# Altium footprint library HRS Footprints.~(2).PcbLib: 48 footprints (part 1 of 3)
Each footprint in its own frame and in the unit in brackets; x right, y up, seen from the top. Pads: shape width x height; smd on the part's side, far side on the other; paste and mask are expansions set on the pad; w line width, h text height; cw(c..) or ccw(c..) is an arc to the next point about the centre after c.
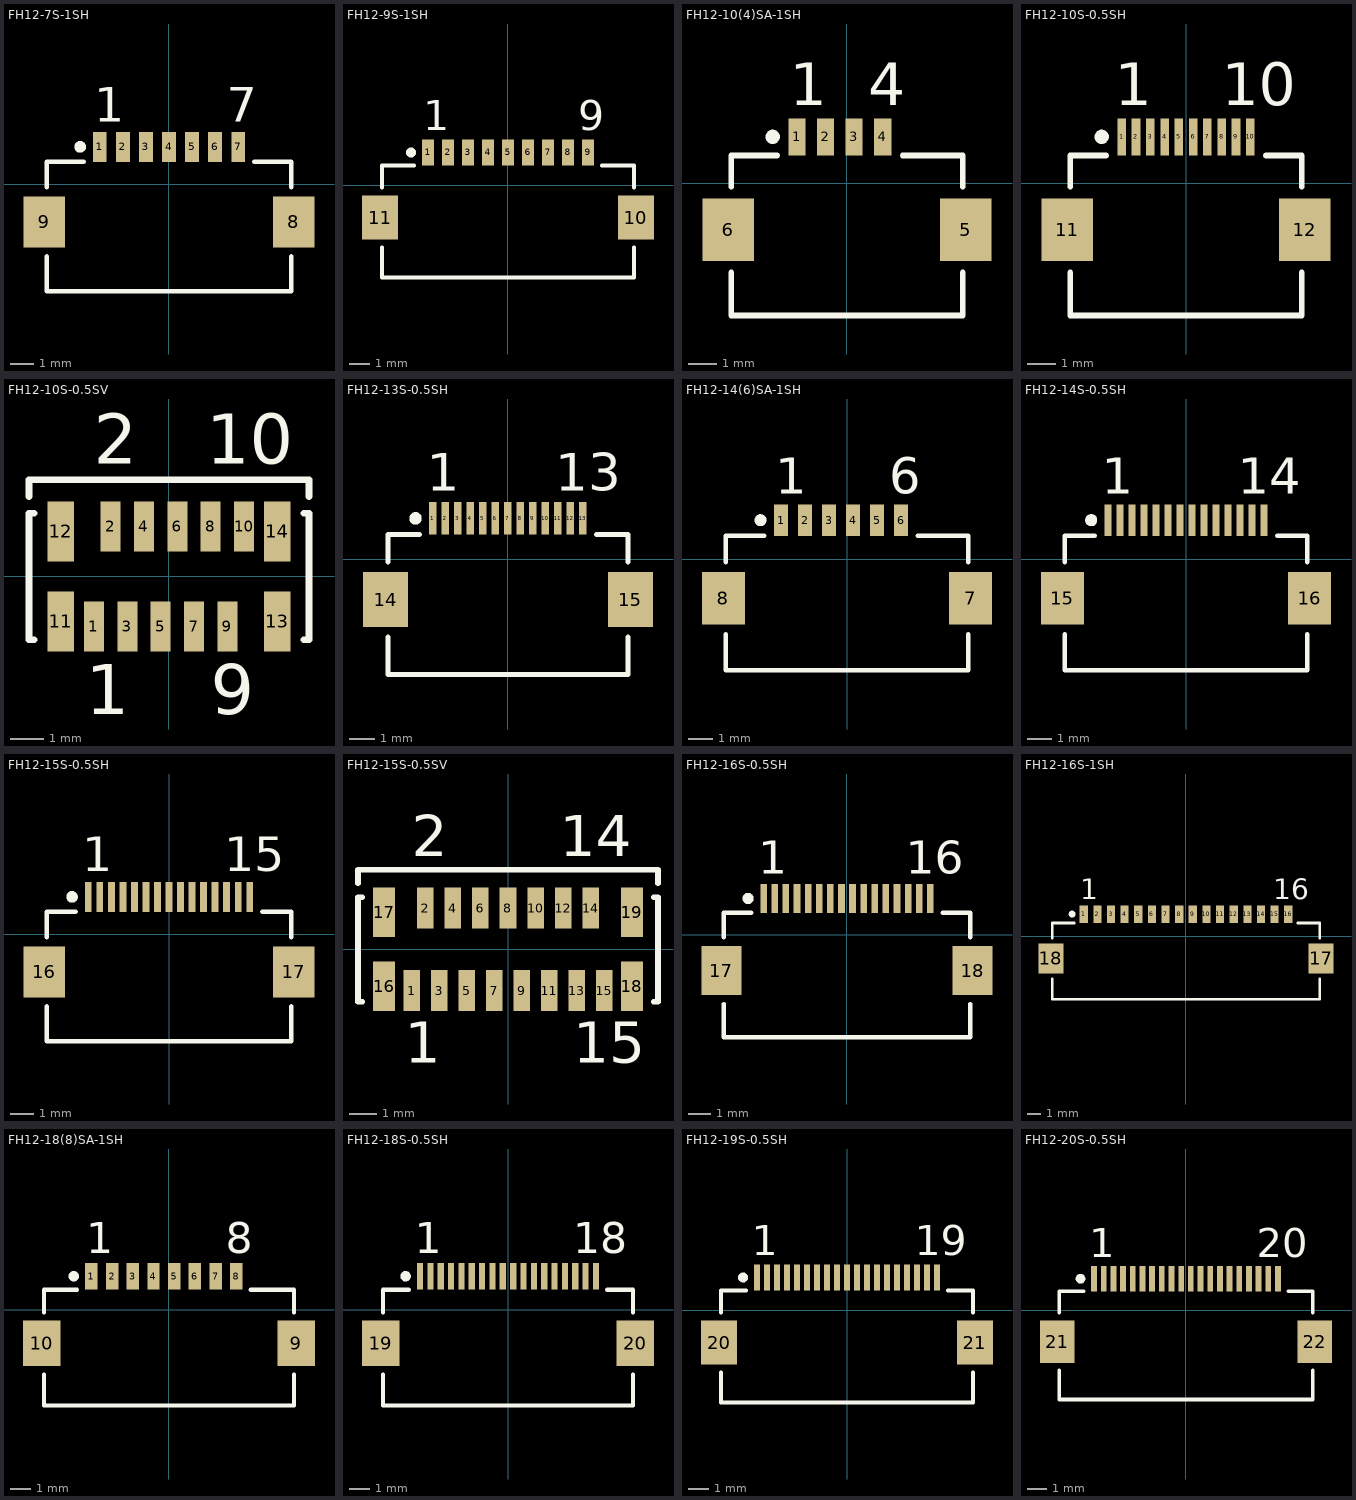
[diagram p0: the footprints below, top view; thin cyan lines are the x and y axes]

## FH12-7S-1SH [mm] "Connector; FH12 Series; 7 Position; 1.0mm Spaced Bottom Standard Contact"
height 2
pads (9):
  rect 0.6x1.3 smd: 1(-3,1.625) 2(-2,1.625) 3(-1,1.625) 4(0,1.625) 5(1,1.625) 6(2,1.625) 7(3,1.625)
  rect 1.8x2.2 smd: 8(5.4,-1.625) 9(-5.4,-1.625)
Top Overlay:
  circle w0.25: c-3.85,1.625 r0.125
  lines w0.2: -5.3,-3.125 -5.3,-4.625 5.3,-4.625 5.3,-3.125 ; -5.3,-0.125 -5.3,0.975 -3.7,0.975 ; 3.7,0.975 5.3,0.975 5.3,-0.125
  text "1" at -3.25,2.725 h1.5
  text "7" at 2.5,2.725 h1.5

## FH12-9S-1SH [mm] "Connector; FH12 Series; 9 Position; 1.0mm Spaced Bottom Standard Contact"
height 2
pads (11):
  rect 0.6x1.3 smd: 1(-4,1.625) 2(-3,1.625) 3(-2,1.625) 4(-1,1.625) 5(0,1.625) 6(1,1.625) 7(2,1.625) 8(3,1.625) 9(4,1.625)
  rect 1.8x2.2 smd: 10(6.4,-1.625) 11(-6.4,-1.625)
Top Overlay:
  circle w0.25: c-4.85,1.625 r0.125
  lines w0.2: -6.3,-3.125 -6.3,-4.625 6.3,-4.625 6.3,-3.125 ; -6.3,-0.125 -6.3,0.975 -4.7,0.975 ; 4.7,0.975 6.3,0.975 6.3,-0.125
  text "1" at -4.25,2.725 h1.5
  text "9" at 3.5,2.725 h1.5

## FH12-10(4)SA-1SH [mm] "Connector; FH12 Series; 4 Position; 1.0mm Spaced Bottom Eccentric Contact"
height 2
pads (6):
  rect 0.6x1.3 smd: 1(-1.75,1.625) 2(-0.75,1.625) 3(0.25,1.625) 4(1.25,1.625)
  rect 1.8x2.2 smd: 5(4.15,-1.625) 6(-4.15,-1.625)
Top Overlay:
  circle w0.25: c-2.6,1.625 r0.125
  lines w0.2: -4.05,-3.125 -4.05,-4.625 4.05,-4.625 4.05,-3.125 ; -4.05,-0.125 -4.05,0.975 -2.45,0.975 ; 1.95,0.975 4.05,0.975 4.05,-0.125
  text "4" at 0.75,2.725 h1.5
  text "1" at -2,2.725 h1.5

## FH12-10S-0.5SH [mm] "Connector; FH12 Series; 10 Position; 0.5mm Spaced Bottom Contact"
height 2
pads (12):
  rect 0.3x1.3 smd: 1(-2.25,1.625) 2(-1.75,1.625) 3(-1.25,1.625) 4(-0.75,1.625) 5(-0.25,1.625) 6(0.25,1.625) 7(0.75,1.625) 8(1.25,1.625) 9(1.75,1.625) 10(2.25,1.625)
  rect 1.8x2.2 smd: 11(-4.15,-1.625) 12(4.15,-1.625)
Top Overlay:
  circle w0.25: c-2.95,1.625 r0.125
  lines w0.2: -4.05,-3.125 -4.05,-4.625 4.05,-4.625 4.05,-3.125 ; -4.05,-0.125 -4.05,0.975 -2.8,0.975 ; 2.8,0.975 4.05,0.975 4.05,-0.125
  text "10" at 1.25,2.725 h1.5
  text "1" at -2.5,2.725 h1.5

## FH12-10S-0.5SV [mm] "Connector; FH12 Series; 10 Position; 0.5mm Spaced Vertical Mounting"
height 4.85
pads (14):
  rect 0.6x1.5 smd: 1(-2.25,-1.5) 2(-1.75,1.5) 3(-1.25,-1.5) 4(-0.75,1.5) 5(-0.25,-1.5) 6(0.25,1.5) 7(0.75,-1.5) 8(1.25,1.5) 9(1.75,-1.5) 10(2.25,1.5)
  rect 0.8x1.8 smd: 11(-3.25,-1.35) 12(-3.25,1.35) 13(3.25,-1.35) 14(3.25,1.35)
Top Overlay:
  lines w0.2: -4.2,2.4 -4.2,2.9 4.2,2.9 4.2,2.4 ; -4.05,-1.9 -4.2,-1.9 -4.2,1.9 -4.05,1.9 ; 4.05,-1.9 4.2,-1.9 4.2,1.9 4.05,1.9
  text "2" at -2.25,3.375 h1.5
  text "1" at -2.5,-4.125 h1.5
  text "10" at 1.125,3.375 h1.5
  text "9" at 1.25,-4.125 h1.5

## FH12-13S-0.5SH [mm] "Connector; FH12 Series; 13 Position; 0.5mm Spaced Bottom Contact"
height 2
pads (15):
  rect 0.3x1.3 smd: 1(-3,1.625) 2(-2.5,1.625) 3(-2,1.625) 4(-1.5,1.625) 5(-1,1.625) 6(-0.5,1.625) 7(0,1.625) 8(0.5,1.625) 9(1,1.625) 10(1.5,1.625) 11(2,1.625) 12(2.5,1.625) 13(3,1.625)
  rect 1.8x2.2 smd: 14(-4.9,-1.625) 15(4.9,-1.625)
Top Overlay:
  circle w0.25: c-3.7,1.625 r0.125
  lines w0.2: -4.8,-3.125 -4.8,-4.625 4.8,-4.625 4.8,-3.125 ; -4.8,-0.125 -4.8,0.975 -3.55,0.975 ; 3.55,0.975 4.8,0.975 4.8,-0.125
  text "13" at 1.9,2.725 h1.5
  text "1" at -3.25,2.725 h1.5

## FH12-14(6)SA-1SH [mm] "Connector; FH12 Series; 6 Position; 1.0mm Spaced Bottom Eccentric Contact"
height 2
pads (8):
  rect 0.6x1.3 smd: 1(-2.75,1.625) 2(-1.75,1.625) 3(-0.75,1.625) 4(0.25,1.625) 5(1.25,1.625) 6(2.25,1.625)
  rect 1.8x2.2 smd: 7(5.15,-1.625) 8(-5.15,-1.625)
Top Overlay:
  circle w0.25: c-3.6,1.625 r0.125
  lines w0.2: -5.05,-3.125 -5.05,-4.625 5.05,-4.625 5.05,-3.125 ; -5.05,-0.125 -5.05,0.975 -3.45,0.975 ; 2.95,0.975 5.05,0.975 5.05,-0.125
  text "1" at -3,2.725 h1.5
  text "6" at 1.75,2.725 h1.5

## FH12-14S-0.5SH [mm] "Connector; FH12 Series; 14 Position; 0.5mm Spaced Bottom Contact"
height 2
pads (16):
  rect 0.3x1.3 smd: 1(-3.25,1.625) 2(-2.75,1.625) 3(-2.25,1.625) 4(-1.75,1.625) 5(-1.25,1.625) 6(-0.75,1.625) 7(-0.25,1.625) 8(0.25,1.625) 9(0.75,1.625) 10(1.25,1.625) 11(1.75,1.625) 12(2.25,1.625) 13(2.75,1.625) 14(3.25,1.625)
  rect 1.8x2.2 smd: 15(-5.15,-1.625) 16(5.15,-1.625)
Top Overlay:
  circle w0.25: c-3.95,1.625 r0.125
  lines w0.2: -5.05,-3.125 -5.05,-4.625 5.05,-4.625 5.05,-3.125 ; -5.05,-0.125 -5.05,0.975 -3.8,0.975 ; 3.8,0.975 5.05,0.975 5.05,-0.125
  text "14" at 2.15,2.725 h1.5
  text "1" at -3.5,2.725 h1.5

## FH12-15S-0.5SH [mm] "Connector; FH12 Series; 15 Position; 0.5mm Spaced Bottom Contact"
height 2
pads (17):
  rect 0.3x1.3 smd: 1(-3.5,1.625) 2(-3,1.625) 3(-2.5,1.625) 4(-2,1.625) 5(-1.5,1.625) 6(-1,1.625) 7(-0.5,1.625) 8(0,1.625) 9(0.5,1.625) 10(1,1.625) 11(1.5,1.625) 12(2,1.625) 13(2.5,1.625) 14(3,1.625) 15(3.5,1.625)
  rect 1.8x2.2 smd: 16(-5.4,-1.625) 17(5.4,-1.625)
Top Overlay:
  circle w0.25: c-4.2,1.625 r0.125
  lines w0.2: -5.3,-3.125 -5.3,-4.625 5.3,-4.625 5.3,-3.125 ; -5.3,-0.125 -5.3,0.975 -4.05,0.975 ; 4.05,0.975 5.3,0.975 5.3,-0.125
  text "15" at 2.4,2.725 h1.5
  text "1" at -3.75,2.725 h1.5

## FH12-15S-0.5SV [mm] "Connector; FH12 Series; 15 Position; 0.5mm Spaced Vertical Mounting"
height 4.85
pads (19):
  rect 0.6x1.5 smd: 1(-3.5,-1.5) 2(-3,1.5) 3(-2.5,-1.5) 4(-2,1.5) 5(-1.5,-1.5) 6(-1,1.5) 7(-0.5,-1.5) 8(0,1.5) 9(0.5,-1.5) 10(1,1.5) 11(1.5,-1.5) 12(2,1.5) 13(2.5,-1.5) 14(3,1.5) 15(3.5,-1.5)
  rect 0.8x1.8 smd: 16(-4.5,-1.35) 17(-4.5,1.35) 18(4.5,-1.35) 19(4.5,1.35)
Top Overlay:
  lines w0.2: -5.45,2.4 -5.45,2.9 5.45,2.9 5.45,2.4 ; -5.3,-1.9 -5.45,-1.9 -5.45,1.9 -5.3,1.9 ; 5.3,-1.9 5.45,-1.9 5.45,1.9 5.3,1.9
  text "14" at 1.875,3.375 h1.5
  text "1" at -3.75,-4.125 h1.5
  text "2" at -3.5,3.375 h1.5
  text "15" at 2.375,-4.125 h1.5

## FH12-16S-0.5SH [mm] "Connector; FH12 Series; 16 Position; 0.5mm Spaced Bottom Contact"
height 2
pads (18):
  rect 0.3x1.3 smd: 1(-3.75,1.625) 2(-3.25,1.625) 3(-2.75,1.625) 4(-2.25,1.625) 5(-1.75,1.625) 6(-1.25,1.625) 7(-0.75,1.625) 8(-0.25,1.625) 9(0.25,1.625) 10(0.75,1.625) 11(1.25,1.625) 12(1.75,1.625) 13(2.25,1.625) 14(2.75,1.625) 15(3.25,1.625) 16(3.75,1.625)
  rect 1.8x2.2 smd: 17(-5.65,-1.625) 18(5.65,-1.625)
Top Overlay:
  circle w0.25: c-4.45,1.625 r0.125
  lines w0.2: -5.55,-3.125 -5.55,-4.625 5.55,-4.625 5.55,-3.125 ; -5.55,-0.125 -5.55,0.975 -4.3,0.975 ; 4.3,0.975 5.55,0.975 5.55,-0.125
  text "1" at -4,2.725 h1.5
  text "16" at 2.65,2.725 h1.5

## FH12-16S-1SH [mm] "Connector; FH12 Series; 16 Position; 1.0mm Spaced Bottom Standard Contact"
height 2
pads (18):
  rect 0.6x1.3 smd: 1(-7.5,1.625) 2(-6.5,1.625) 3(-5.5,1.625) 4(-4.5,1.625) 5(-3.5,1.625) 6(-2.5,1.625) 7(-1.5,1.625) 8(-0.5,1.625) 9(0.5,1.625) 10(1.5,1.625) 11(2.5,1.625) 12(3.5,1.625) 13(4.5,1.625) 14(5.5,1.625) 15(6.5,1.625) 16(7.5,1.625)
  rect 1.8x2.2 smd: 17(9.9,-1.625) 18(-9.9,-1.625)
Top Overlay:
  circle w0.25: c-8.35,1.625 r0.125
  lines w0.2: -9.8,-3.125 -9.8,-4.625 9.8,-4.625 9.8,-3.125 ; -9.8,-0.125 -9.8,0.975 -8.2,0.975 ; 8.2,0.975 9.8,0.975 9.8,-0.125
  text "16" at 6.4,2.725 h1.5
  text "1" at -7.75,2.725 h1.5

## FH12-18(8)SA-1SH [mm] "Connector; FH12 Series; 8 Position; 1.0mm Spaced Bottom Eccentric Contact"
height 2
pads (10):
  rect 0.6x1.3 smd: 1(-3.75,1.625) 2(-2.75,1.625) 3(-1.75,1.625) 4(-0.75,1.625) 5(0.25,1.625) 6(1.25,1.625) 7(2.25,1.625) 8(3.25,1.625)
  rect 1.8x2.2 smd: 9(6.15,-1.625) 10(-6.15,-1.625)
Top Overlay:
  circle w0.25: c-4.6,1.625 r0.125
  lines w0.2: -6.05,-3.125 -6.05,-4.625 6.05,-4.625 6.05,-3.125 ; -6.05,-0.125 -6.05,0.975 -4.45,0.975 ; 3.95,0.975 6.05,0.975 6.05,-0.125
  text "8" at 2.75,2.725 h1.5
  text "1" at -4,2.725 h1.5

## FH12-18S-0.5SH [mm] "Connector; FH12 Series; 18 Position; 0.5mm Spaced Bottom Contact"
height 2
pads (20):
  rect 0.3x1.3 smd: 1(-4.25,1.625) 2(-3.75,1.625) 3(-3.25,1.625) 4(-2.75,1.625) 5(-2.25,1.625) 6(-1.75,1.625) 7(-1.25,1.625) 8(-0.75,1.625) 9(-0.25,1.625) 10(0.25,1.625) 11(0.75,1.625) 12(1.25,1.625) 13(1.75,1.625) 14(2.25,1.625) 15(2.75,1.625) 16(3.25,1.625) 17(3.75,1.625) 18(4.25,1.625)
  rect 1.8x2.2 smd: 19(-6.15,-1.625) 20(6.15,-1.625)
Top Overlay:
  circle w0.25: c-4.95,1.625 r0.125
  lines w0.2: -6.05,-3.125 -6.05,-4.625 6.05,-4.625 6.05,-3.125 ; -6.05,-0.125 -6.05,0.975 -4.8,0.975 ; 4.8,0.975 6.05,0.975 6.05,-0.125
  text "1" at -4.5,2.725 h1.5
  text "18" at 3.15,2.725 h1.5

## FH12-19S-0.5SH [mm] "Connector; FH12 Series; 19 Position; 0.5mm Spaced Bottom Contact"
height 2
pads (21):
  rect 0.3x1.3 smd: 1(-4.5,1.625) 2(-4,1.625) 3(-3.5,1.625) 4(-3,1.625) 5(-2.5,1.625) 6(-2,1.625) 7(-1.5,1.625) 8(-1,1.625) 9(-0.5,1.625) 10(0,1.625) 11(0.5,1.625) 12(1,1.625) 13(1.5,1.625) 14(2,1.625) 15(2.5,1.625) 16(3,1.625) 17(3.5,1.625) 18(4,1.625) 19(4.5,1.625)
  rect 1.8x2.2 smd: 20(-6.4,-1.625) 21(6.4,-1.625)
Top Overlay:
  circle w0.25: c-5.2,1.625 r0.125
  lines w0.2: -6.3,-3.125 -6.3,-4.625 6.3,-4.625 6.3,-3.125 ; -6.3,-0.125 -6.3,0.975 -5.05,0.975 ; 5.05,0.975 6.3,0.975 6.3,-0.125
  text "19" at 3.4,2.725 h1.5
  text "1" at -4.75,2.725 h1.5

## FH12-20S-0.5SH [mm] "Connector; FH12 Series; 20 Position; 0.5mm Spaced Bottom Contact"
height 2
pads (22):
  rect 0.3x1.3 smd: 1(-4.75,1.625) 2(-4.25,1.625) 3(-3.75,1.625) 4(-3.25,1.625) 5(-2.75,1.625) 6(-2.25,1.625) 7(-1.75,1.625) 8(-1.25,1.625) 9(-0.75,1.625) 10(-0.25,1.625) 11(0.25,1.625) 12(0.75,1.625) 13(1.25,1.625) 14(1.75,1.625) 15(2.25,1.625) 16(2.75,1.625) 17(3.25,1.625) 18(3.75,1.625) 19(4.25,1.625) 20(4.75,1.625)
  rect 1.8x2.2 smd: 21(-6.65,-1.625) 22(6.65,-1.623)
Top Overlay:
  circle w0.25: c-5.45,1.625 r0.125
  lines w0.2: -6.55,-3.123 -6.55,-4.623 6.55,-4.623 6.55,-3.123 ; -6.55,-0.123 -6.55,0.977 -5.3,0.977 ; 5.3,0.977 6.55,0.977 6.55,-0.123
  text "1" at -5,2.725 h1.5
  text "20" at 3.65,2.725 h1.5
